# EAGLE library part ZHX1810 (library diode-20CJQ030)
ZILOG ZHX1810 Slim Series SIR Transceiver Description: The ZILOG ZHX1810 is a low-profile version of ZiLOG's popular ZHX1010 1-meter transceiver. The transceiver is mechanically enhanced for ultra compact, power-conscious portable products, such as mobile phones, portable printers, handheld computers, and personal data assistants (PDAs). Designed to operate using the IrDA-Data mode, the transceiver combines an infrared emitting diode (IRED) emitter, a PIN photodiode detector, a digital AC coupled LED driver, and a receiver/decoder in a single package. The ZILOG ZHX1810 provides an efficient implementation of the SIR standard in a small-outline footprint format. Application circuit space is also minimized, as only three components are required. ZHX1810 also features an independently controlled shutdown that minimizes current draw to a maximum of 1 µA. Features: Compliant to IrDA Data Specification SIR Wide power supply voltage range, 2.4 to 5.5 V Minimum link distance, 1 M Low-power, listening current, 90 µA (typical) at 3.0 V Slim form factor (9.1 mm long x 3.8 mm wide x 2.73 mm high) Only two external components required Extended operating temperature range (-30 °C to +85 °C) Meets IEC 825-1 Class 1 Eye Safety Specifications Please send any comments to: messi@users.sourceforge.net
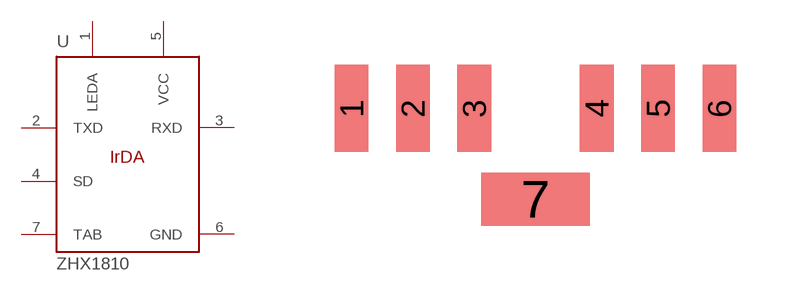
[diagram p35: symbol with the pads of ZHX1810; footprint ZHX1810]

Designator prefix U

## ZHX1810  [ZHX1810]
1  LEDA  pwr
2  TXD  in
3  RXD  out
4  SD  in
5  VCC  pwr
6  GND  pwr
7  TAB  pwr

## Footprint ZHX1810 (pad centres in mm)
Zilog packaging for the IrDA device ZHX1810 Please send any comments to: messi@users.sourceforge.net
smd 0.85 x 2.2: 1 -4.65,0.9; 2 -3.1,0.9; 3 -1.55,0.9; 4 1.55,0.9; 5 3.1,0.9; 6 4.65,0.9
smd 2.75 x 1.35: 7 0,-1.4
